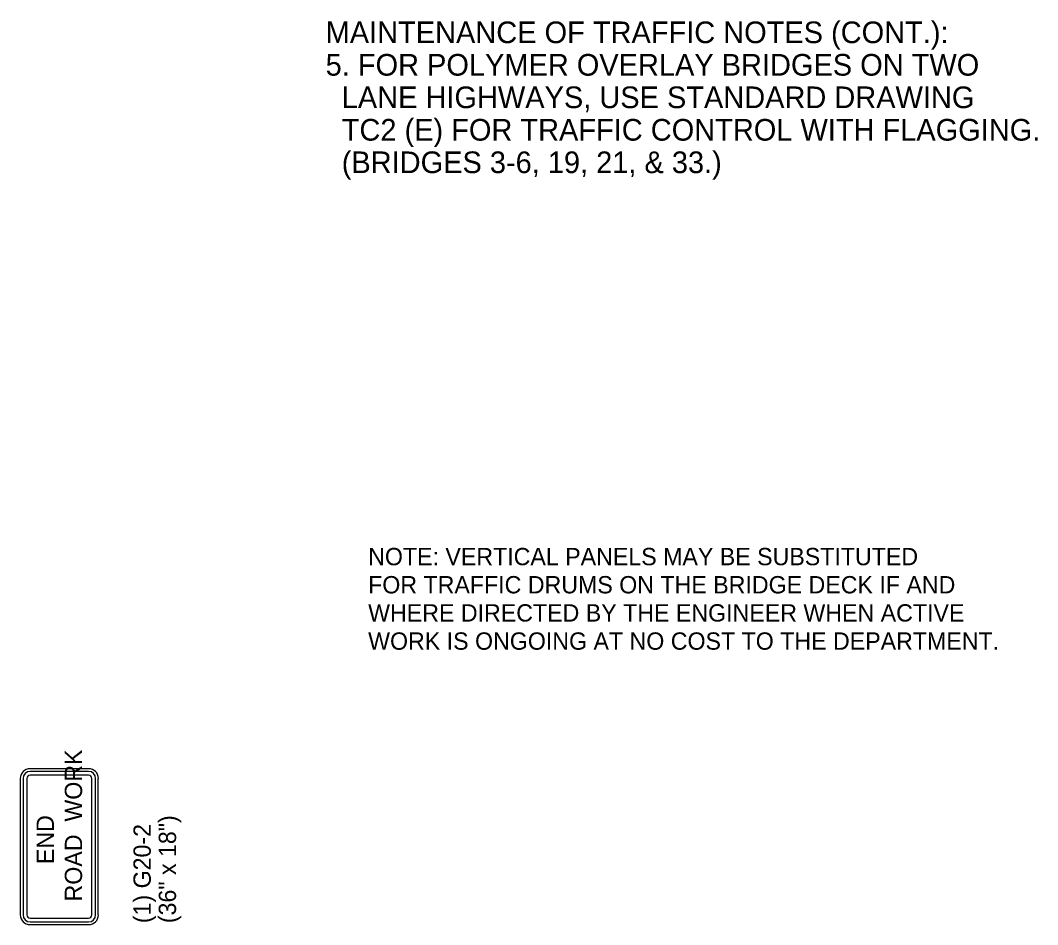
# Model space of a CAD drawing. Extents: x 1930579 to 1934718, y 596452 to 597844.
# Drawn here: x 1932817.2 to 1933169.3, y 597530.6 to 597843.7 of the extents above; entities that cross this region are included whole.
import ezdxf

# ---------------------------------------------------------------- set-up
doc = ezdxf.new("R2010")
doc.units = 0
doc.layers.add('P_TC_Signs_Temporary', color=7, linetype='Continuous')
doc.layers.add('R_Annotation', color=7, linetype='Continuous')

msp = doc.modelspace()

# ---------------------------------------------------------------- linework, layer by layer
at = {"layer": 'P_TC_Signs_Temporary'}
for p, q in [((1932840.8, 597584.57), (1932820.55, 597584.57)), ((1932817.17, 597581.2), (1932817.17, 597533.95)), ((1932818.11, 597581.2), (1932818.11, 597533.95)), ((1932819.42, 597581.2), (1932819.42, 597533.95)), ((1932840.8, 597583.63), (1932820.55, 597583.63)), ((1932840.8, 597582.32), (1932820.55, 597582.32)), ((1932841.92, 597533.95), (1932841.92, 597581.2)), ((1932843.24, 597533.95), (1932843.24, 597581.2)), ((1932844.17, 597533.95), (1932844.17, 597581.2)), ((1932820.55, 597532.82), (1932840.8, 597532.82)), ((1932820.55, 597531.51), (1932840.8, 597531.51)), ((1932820.55, 597530.57), (1932840.8, 597530.57))]:
    msp.add_line(p, q, dxfattribs=at)
for centre, radius, start, end in [((1932820.55, 597581.2), 3.38, 90, 180), ((1932840.8, 597581.2), 3.38, 360, 90), ((1932820.55, 597581.2), 2.44, 90, 180), ((1932820.55, 597581.2), 1.13, 90, 180), ((1932840.8, 597581.2), 2.44, 360, 90), ((1932840.8, 597581.2), 1.13, 360, 90), ((1932820.55, 597533.95), 3.38, 180, 270), ((1932820.55, 597533.95), 2.44, 180, 270), ((1932820.55, 597533.95), 1.13, 180, 270), ((1932840.8, 597533.95), 2.44, 270, 360), ((1932840.8, 597533.95), 1.13, 270, 360), ((1932840.8, 597533.95), 3.38, 270, 360)]:
    msp.add_arc(centre, radius, start, end, dxfattribs=at)

# ---------------------------------------------------------------- texts
for s, p in [('ROAD  WORK', (1932838.55, 597538.61)), ('END', (1932828.8, 597551.54))]:
    msp.add_text(s, height=6, rotation=90, dxfattribs=at).set_placement(p)
at = {"layer": 'R_Annotation'}
for s, height, rotation, p in [('MAINTENANCE OF TRAFFIC NOTES (CONT.): ', 7.5, 360, (1932922.86, 597835.77)), ('5. FOR POLYMER OVERLAY BRIDGES ON TWO', 7.5, 360, (1932922.86, 597824.52)), ('  LANE HIGHWAYS, USE STANDARD DRAWING', 7.5, 360, (1932922.86, 597813.27)), ('  TC2 (E) FOR TRAFFIC CONTROL WITH FLAGGING.  ', 7.5, 360, (1932922.86, 597802.02)), ('  (BRIDGES 3-6, 19, 21, & 33.)', 7.5, 360, (1932922.86, 597790.77)), ('NOTE: VERTICAL PANELS MAY BE SUBSTITUTED', 6, 360, (1932937.57, 597655.01)), ('FOR TRAFFIC DRUMS ON THE BRIDGE DECK IF AND', 6, 360, (1932937.57, 597645.26)), ('WHERE DIRECTED BY THE ENGINEER WHEN ACTIVE', 6, 360, (1932937.57, 597635.51)), ('WORK IS ONGOING AT NO COST TO THE DEPARTMENT.', 6, 360, (1932937.57, 597625.76)), ('(36" x 18")', 5.9996, 90, (1932871.08, 597531.09)), ('(1) G20-2', 6, 90, (1932862.33, 597531.09))]:
    msp.add_text(s, height=height, rotation=rotation, dxfattribs=at).set_placement(p)

doc.saveas('drawing.dxf')
